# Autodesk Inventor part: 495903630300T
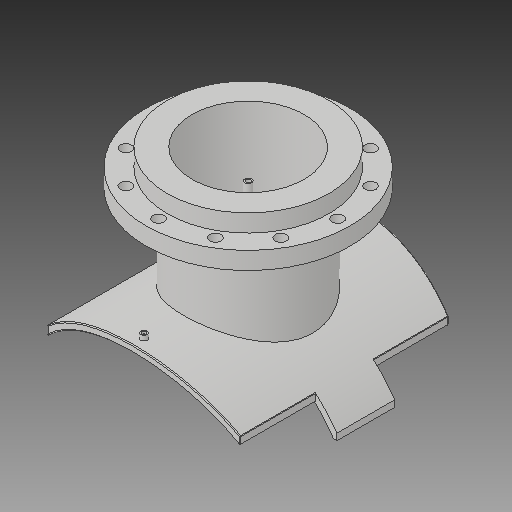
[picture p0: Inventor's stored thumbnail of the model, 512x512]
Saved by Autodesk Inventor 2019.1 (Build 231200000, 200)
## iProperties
Created: 2017-10
Part Number: 495903630300T
Material: Generic
Description: PLASSON FLANGED BRANCH SADDLE 630X300
Document SubType Name: Modeling
Designer: KIM
Mass: 2339.99 g
Surface Area: 3251.55 cm^2
Volume: 2339.99 cm^3
Density: 1 g/cm^3
Appearance: Default
Author: KIM
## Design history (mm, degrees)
derived "495904_495903.ipt"
feature "Solid1::495904_495903.ipt"
feature "Solid2::495904_495903.ipt"
tag "TaggingFeature1"
body "Solid1"
other parameters: "d1" = 15, "d2" = 441, "d4" = 0, "d6" = 132.5, "d7" = 0, "d12" = 340.6, "d13" = 14, "d14" = 238.5, "d16" = 5 deg, "d18" = 4, "d19" = 14, "d20" = 0, "d21" = 3, "d22" = 0, "d23" = 605, "d36" = 238.5, "d38" = 0, "d39" = 2, "d41" = 257, "d43" = 467, "d46" = 296, "d47" = 16, "d48" = 10.4, "d49" = 192.5, "d51" = 642.6, "d53" = 0, "d54" = 26, "d55" = 205, "d57" = 0, "d59" = 360 deg, "d63" = 0, "d66" = 275, "d67" = 15, "d68" = 137.5, "d70" = 0, "d71" = 2, "H_" = 275, "x_" = 15, "D_" = 16, "DN_" = 257, "D_1" = 467, "s_" = 26
